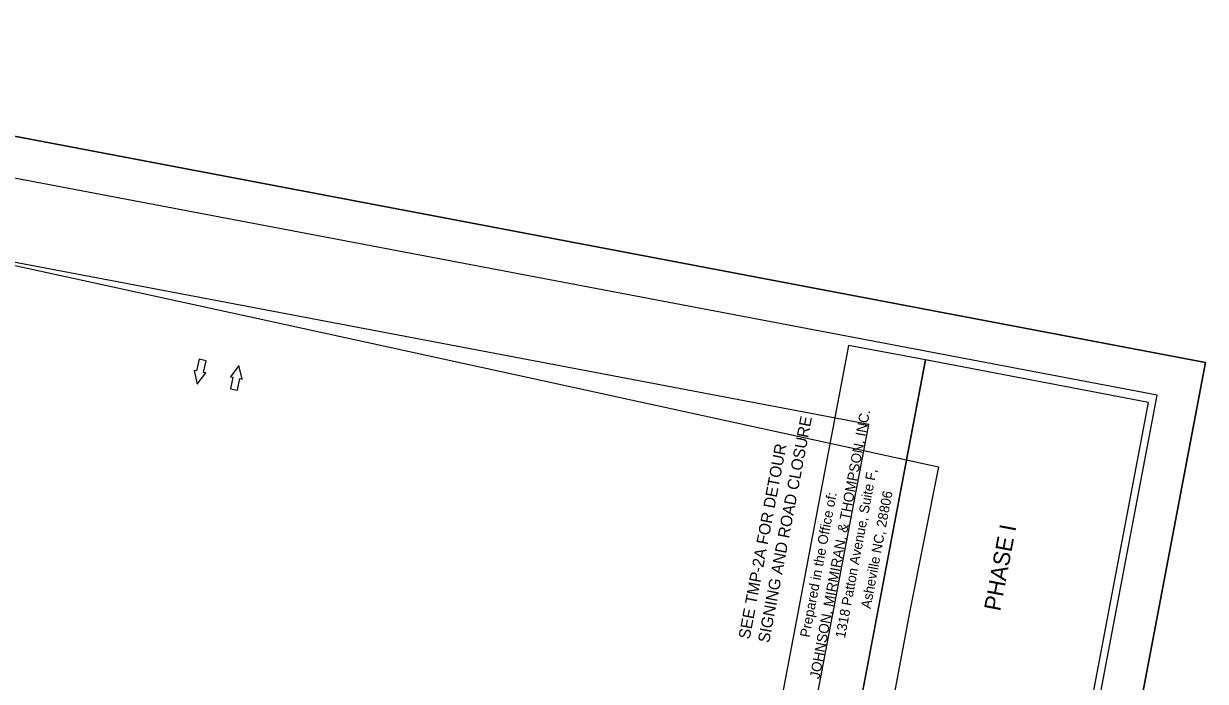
# Model space of a CAD drawing. Extents: x 1615642 to 1617075, y 899305 to 901510.
# Drawn here: x 1616360 to 1617075, y 900770 to 901168 of the extents above; entities that cross this region are included whole.
import ezdxf

# ---------------------------------------------------------------- set-up
doc = ezdxf.new("R2010")
doc.units = 0
for name, color, linetype in [('DEV BORDER CELL', 7, 'Continuous'), ('DEV DIRECTION OF TRAFFIC FLOW ARROW CELL', 7, 'Continuous'), ('Prop DSN Text', 7, 'Continuous'), ('Scratch_Level_0', 7, 'Continuous'), ('Sheet Clip Boundary CELL', 7, 'Continuous'), ('Sheet Plan CELL', 7, 'Continuous'), ('Sheet Plot Border Outside CELL', 7, 'Continuous'), ('Sheet Sticker Preliminary CELL', 7, 'Continuous'), ('Sheet Title CELL', 7, 'Continuous')]:
    doc.layers.add(name, color=color, linetype=linetype)

msp = doc.modelspace()

# ---------------------------------------------------------------- linework, layer by layer
at = {"layer": 'DEV BORDER CELL'}
for points in [[(1616014.55, 901139.21), (1615734.74, 899665.53), (1616766.32, 899469.67), (1617046.12, 900943.35)], [(1616905.88, 900964.73), (1616861.86, 900732.87), (1616996.95, 900707.23), (1617040.97, 900939.08)]]:
    msp.add_lwpolyline(points, close=True, dxfattribs=at)
at = {"layer": 'DEV DIRECTION OF TRAFFIC FLOW ARROW CELL'}
for p, q in [((1616465.76, 900965.16), (1616464.24, 900958.12)), ((1616470.01, 900964.24), (1616465.76, 900965.16)), ((1616464.24, 900958.12), (1616462.79, 900958.43)), ((1616462.79, 900958.43), (1616464.72, 900950.08)), ((1616468.49, 900957.2), (1616470.01, 900964.24)), ((1616489.8, 900961.48), (1616484.77, 900954.55)), ((1616491.94, 900953.18), (1616489.8, 900961.48)), ((1616464.72, 900950.08), (1616469.93, 900956.89)), ((1616469.93, 900956.89), (1616468.49, 900957.2)), ((1616484.77, 900954.55), (1616486.22, 900954.27)), ((1616486.22, 900954.27), (1616484.87, 900947.2)), ((1616489.14, 900946.38), (1616490.49, 900953.46)), ((1616490.49, 900953.46), (1616491.94, 900953.18)), ((1616484.87, 900947.2), (1616489.14, 900946.38))]:
    msp.add_line(p, q, dxfattribs=at)
at = {"layer": 'Scratch_Level_0'}
msp.add_lwpolyline([(1616054.34, 901080.76), (1615793.19, 899705.33), (1616726.52, 899528.12), (1616890.46, 900391.55), (1616774.26, 900413.61), (1616871.48, 900925.61)], close=True, dxfattribs=at)
at = {"layer": 'Sheet Clip Boundary CELL'}
msp.add_lwpolyline([(1616176.29, 901060.7), (1616913.78, 900900.04), (1616896.28, 900812.91), (1616872.94, 900688.21), (1616835.87, 900695.21), (1616753.94, 900262.18), (1616898.09, 900233.43), (1616663.91, 899565.73), (1616252.62, 899604.04), (1615894.68, 899796.73), (1615981.58, 900932.46), (1616145.94, 900899.57)], close=True, dxfattribs=at)
at = {"layer": 'Sheet Plan CELL'}
msp.add_lwpolyline([(1616859.19, 900973.59), (1616804.79, 900687.04), (1616851.47, 900678.18), (1616905.88, 900964.73)], close=True, dxfattribs=at)
at = {"layer": 'Sheet Plot Border Outside CELL'}
for points in [[(1616760.47, 899304.87), (1615679.78, 899510.06), (1615994.65, 901168.43), (1617075.34, 900963.24)], [(1616760.47, 899304.87), (1617075.34, 900963.24), (1615994.65, 901168.43), (1615679.78, 899510.06)]]:
    msp.add_lwpolyline(points, close=True, dxfattribs=at)

# ---------------------------------------------------------------- texts
at = {"layer": 'Prop DSN Text'}
for s, p in [('SIGNING AND ROAD CLOSURE', (1616811.09, 900793.05)), ('SEE TMP-2A FOR DETOUR', (1616799.31, 900795.28))]:
    msp.add_text(s, height=7, rotation=79.2494, dxfattribs=at).set_placement(p)
at = {"layer": 'Sheet Sticker Preliminary CELL'}
msp.add_text('PHASE I', height=10, rotation=79.24937, dxfattribs=at).set_placement((1616951.02, 900812.2))
at = {"layer": 'Sheet Title CELL'}
for s, height, p in [('JOHNSON, MIRMIRAN, & THOMPSON, INC.', 6.0929, (1616841.6, 900771.3)), ('1318 Patton Avenue, Suite F,', 5.9679, (1616857.01, 900795.9)), ('Prepared in the Office of:', 5.9987, (1616835.57, 900796.39)), ('Asheville NC, 28806', 5.9679, (1616872.53, 900813.77))]:
    msp.add_text(s, height=height, rotation=79.301, dxfattribs=at).set_placement(p)

doc.saveas('drawing.dxf')
